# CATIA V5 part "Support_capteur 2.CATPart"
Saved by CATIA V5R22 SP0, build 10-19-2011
Part number: Support_capteur 2
Bounding box of the stored display mesh (mm): x -42.5 to 42.5, y 0 to 5, z -10 to 10
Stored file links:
  D:\PER\CAO_PER_MODIF_2025\CAO_PER_pick&place_2024P\Cadre\Support_capteur 2.CATPart
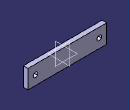
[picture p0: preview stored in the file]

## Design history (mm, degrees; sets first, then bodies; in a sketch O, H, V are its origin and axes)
Body1 (main body)
  Sketch1 on zx-plane, origin (0, 0, 0), H (-1, 0, 0), V (0, 0, 1)
    line L1 (42.5, 10) -> (42.5, -10)
    line L2 (42.5, -10) -> (-42.5, -10)
    line L3 (-42.5, -10) -> (-42.5, 10)
    line L4 (-42.5, 10) -> (42.5, 10)
    length L4 = 85
    length L1 = 20
    vertical: L1 V, L3 V
    horizontal: L2 H, L4 H
    equidistance: L1 L3 O, L2 L4 O
  Pad1: profile Sketch1, direction (0, 1, 0), length 5
  Sketch2 on end face of Pad1, origin (-30.6213, 5, -4.6754), H (1, 0, 0), V (0, 0, -1)
    point P1 (-3.8787, -4.6754)
    axis line L1 (96.1656, -4.6754) -> (-31.2858, -4.6754)
    reference projected line E1 (73.1213, 5.3246) -> (-11.8787, 5.3246) from edge [face of Pad1 from Sketch1.L2 | end face of Pad1]
    reference projected line E2 (-11.8787, -14.6754) -> (73.1213, -14.6754) from edge [face of Pad1 from Sketch1.L4 | end face of Pad1]
    reference projected line E3 (-11.8787, 5.3246) -> (-11.8787, -14.6754) from edge [face of Pad1 from Sketch1.L1 | end face of Pad1]
    distance P1 E3 = 8
    horizontal: L1 H
    symmetry: E1 E2 L1
    coincidence: P1 L1
  Hole1: placed by Sketch2, at (-34.5, 5, 0) direction (0, -1, 0), diameter 4.917, depth 10, threaded "M6", thread diameter 6, thread depth 10, pitch 1
  Mirror1: of Hole1, about yz-plane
